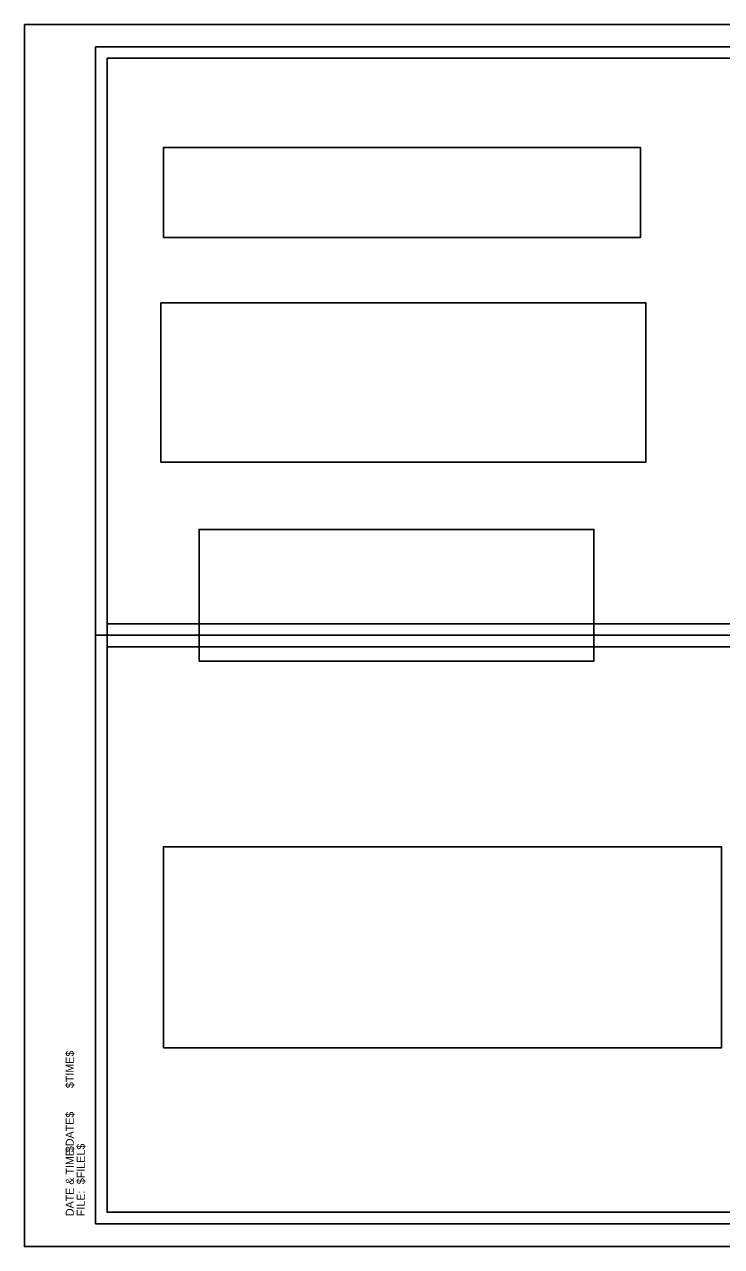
# Model space of a CAD drawing. Extents: x 1369904 to 1372237, y 380119 to 380332.
# Drawn here: x 1370403.5 to 1370525.1, y 380119.1 to 380332.4 of the extents above; entities that cross this region are included whole.
import ezdxf

# ---------------------------------------------------------------- set-up
doc = ezdxf.new("R2010")
doc.units = 0
for name, color, linetype in [('Default', 7, 'Continuous'), ('R_Border', 7, 'Continuous'), ('R_Border Notes', 7, 'Continuous'), ('R_Border Plan-Plan', 7, 'Continuous'), ('R_No Plot', 7, 'Continuous')]:
    doc.layers.add(name, color=color, linetype=linetype)

msp = doc.modelspace()

# ---------------------------------------------------------------- linework, layer by layer
at = {"layer": 'Default'}
for points in [[(1370427.76, 380295.23), (1370511, 380295.23), (1370511, 380310.91), (1370427.76, 380310.91)], [(1370427.32, 380255.99), (1370511.9, 380255.99), (1370511.9, 380283.82), (1370427.32, 380283.82)], [(1370433.97, 380221.27), (1370502.87, 380221.27), (1370502.87, 380244.24), (1370433.97, 380244.24)], [(1370427.75, 380153.73), (1370525.09, 380153.73), (1370525.09, 380188.84), (1370427.75, 380188.84)]]:
    msp.add_lwpolyline(points, close=True, dxfattribs=at)
at = {"layer": 'R_Border'}
for p, q in [((1370415.92, 380328.5), (1370732.1, 380328.5)), ((1370415.92, 380123.04), (1370415.92, 380328.5)), ((1370415.92, 380123.04), (1370415.92, 380123.04)), ((1370732.1, 380123.04), (1370415.92, 380123.04))]:
    msp.add_line(p, q, dxfattribs=at)
at = {"layer": 'R_Border Plan-Plan'}
msp.add_line((1370415.92, 380225.77), (1370732.1, 380225.77), dxfattribs=at)
at = {"layer": 'R_No Plot'}
for points in [[(1370403.52, 380332.4), (1370736.86, 380332.4), (1370736.86, 380119.06), (1370403.52, 380119.06)], [(1370730.1, 380227.77), (1370417.92, 380227.77), (1370417.92, 380326.5), (1370667.46, 380326.5), (1370667.46, 380316.62), (1370685, 380316.62), (1370709.1, 380316.62), (1370709.1, 380294.29), (1370730.1, 380294.29)], [(1370417.92, 380326.5), (1370667.46, 380326.5), (1370667.46, 380316.62), (1370685, 380316.62), (1370709.1, 380316.62), (1370709.1, 380294.29), (1370730.1, 380294.29), (1370730.1, 380125.04), (1370417.92, 380125.04)], [(1370417.92, 380223.77), (1370730.1, 380223.77), (1370730.1, 380125.04), (1370417.92, 380125.04)]]:
    msp.add_lwpolyline(points, close=True, dxfattribs=at)

# ---------------------------------------------------------------- texts
at = {"layer": 'R_Border Notes'}
for s, height, p in [('$TIME$', 1.397, (1370412.12, 380146.72)), ('$DATE$', 1.397, (1370412.12, 380135.54)), ('DATE & TIME:', 1.3968, (1370412.12, 380124.37)), ('$FILEL$', 1.397, (1370414.04, 380129.95)), ('FILE: ', 1.397, (1370414.04, 380124.37))]:
    msp.add_text(s, height=height, rotation=90, dxfattribs=at).set_placement(p)

doc.saveas('drawing.dxf')
